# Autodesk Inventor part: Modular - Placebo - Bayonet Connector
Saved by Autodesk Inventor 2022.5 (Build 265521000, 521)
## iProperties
Created: 2025-01
Part Number: Modular - Placebo - Bayonet Connector
Material: Generic
Document SubType Name: Modeling
Designer: AdminForWorker
Density: 1 g/cm^3
Appearance: Default
Title: Modular - Placebo - Bayonet Connector v4
Author: AdminForWorker
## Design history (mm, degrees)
feature "Body1"
body "Solid1"
